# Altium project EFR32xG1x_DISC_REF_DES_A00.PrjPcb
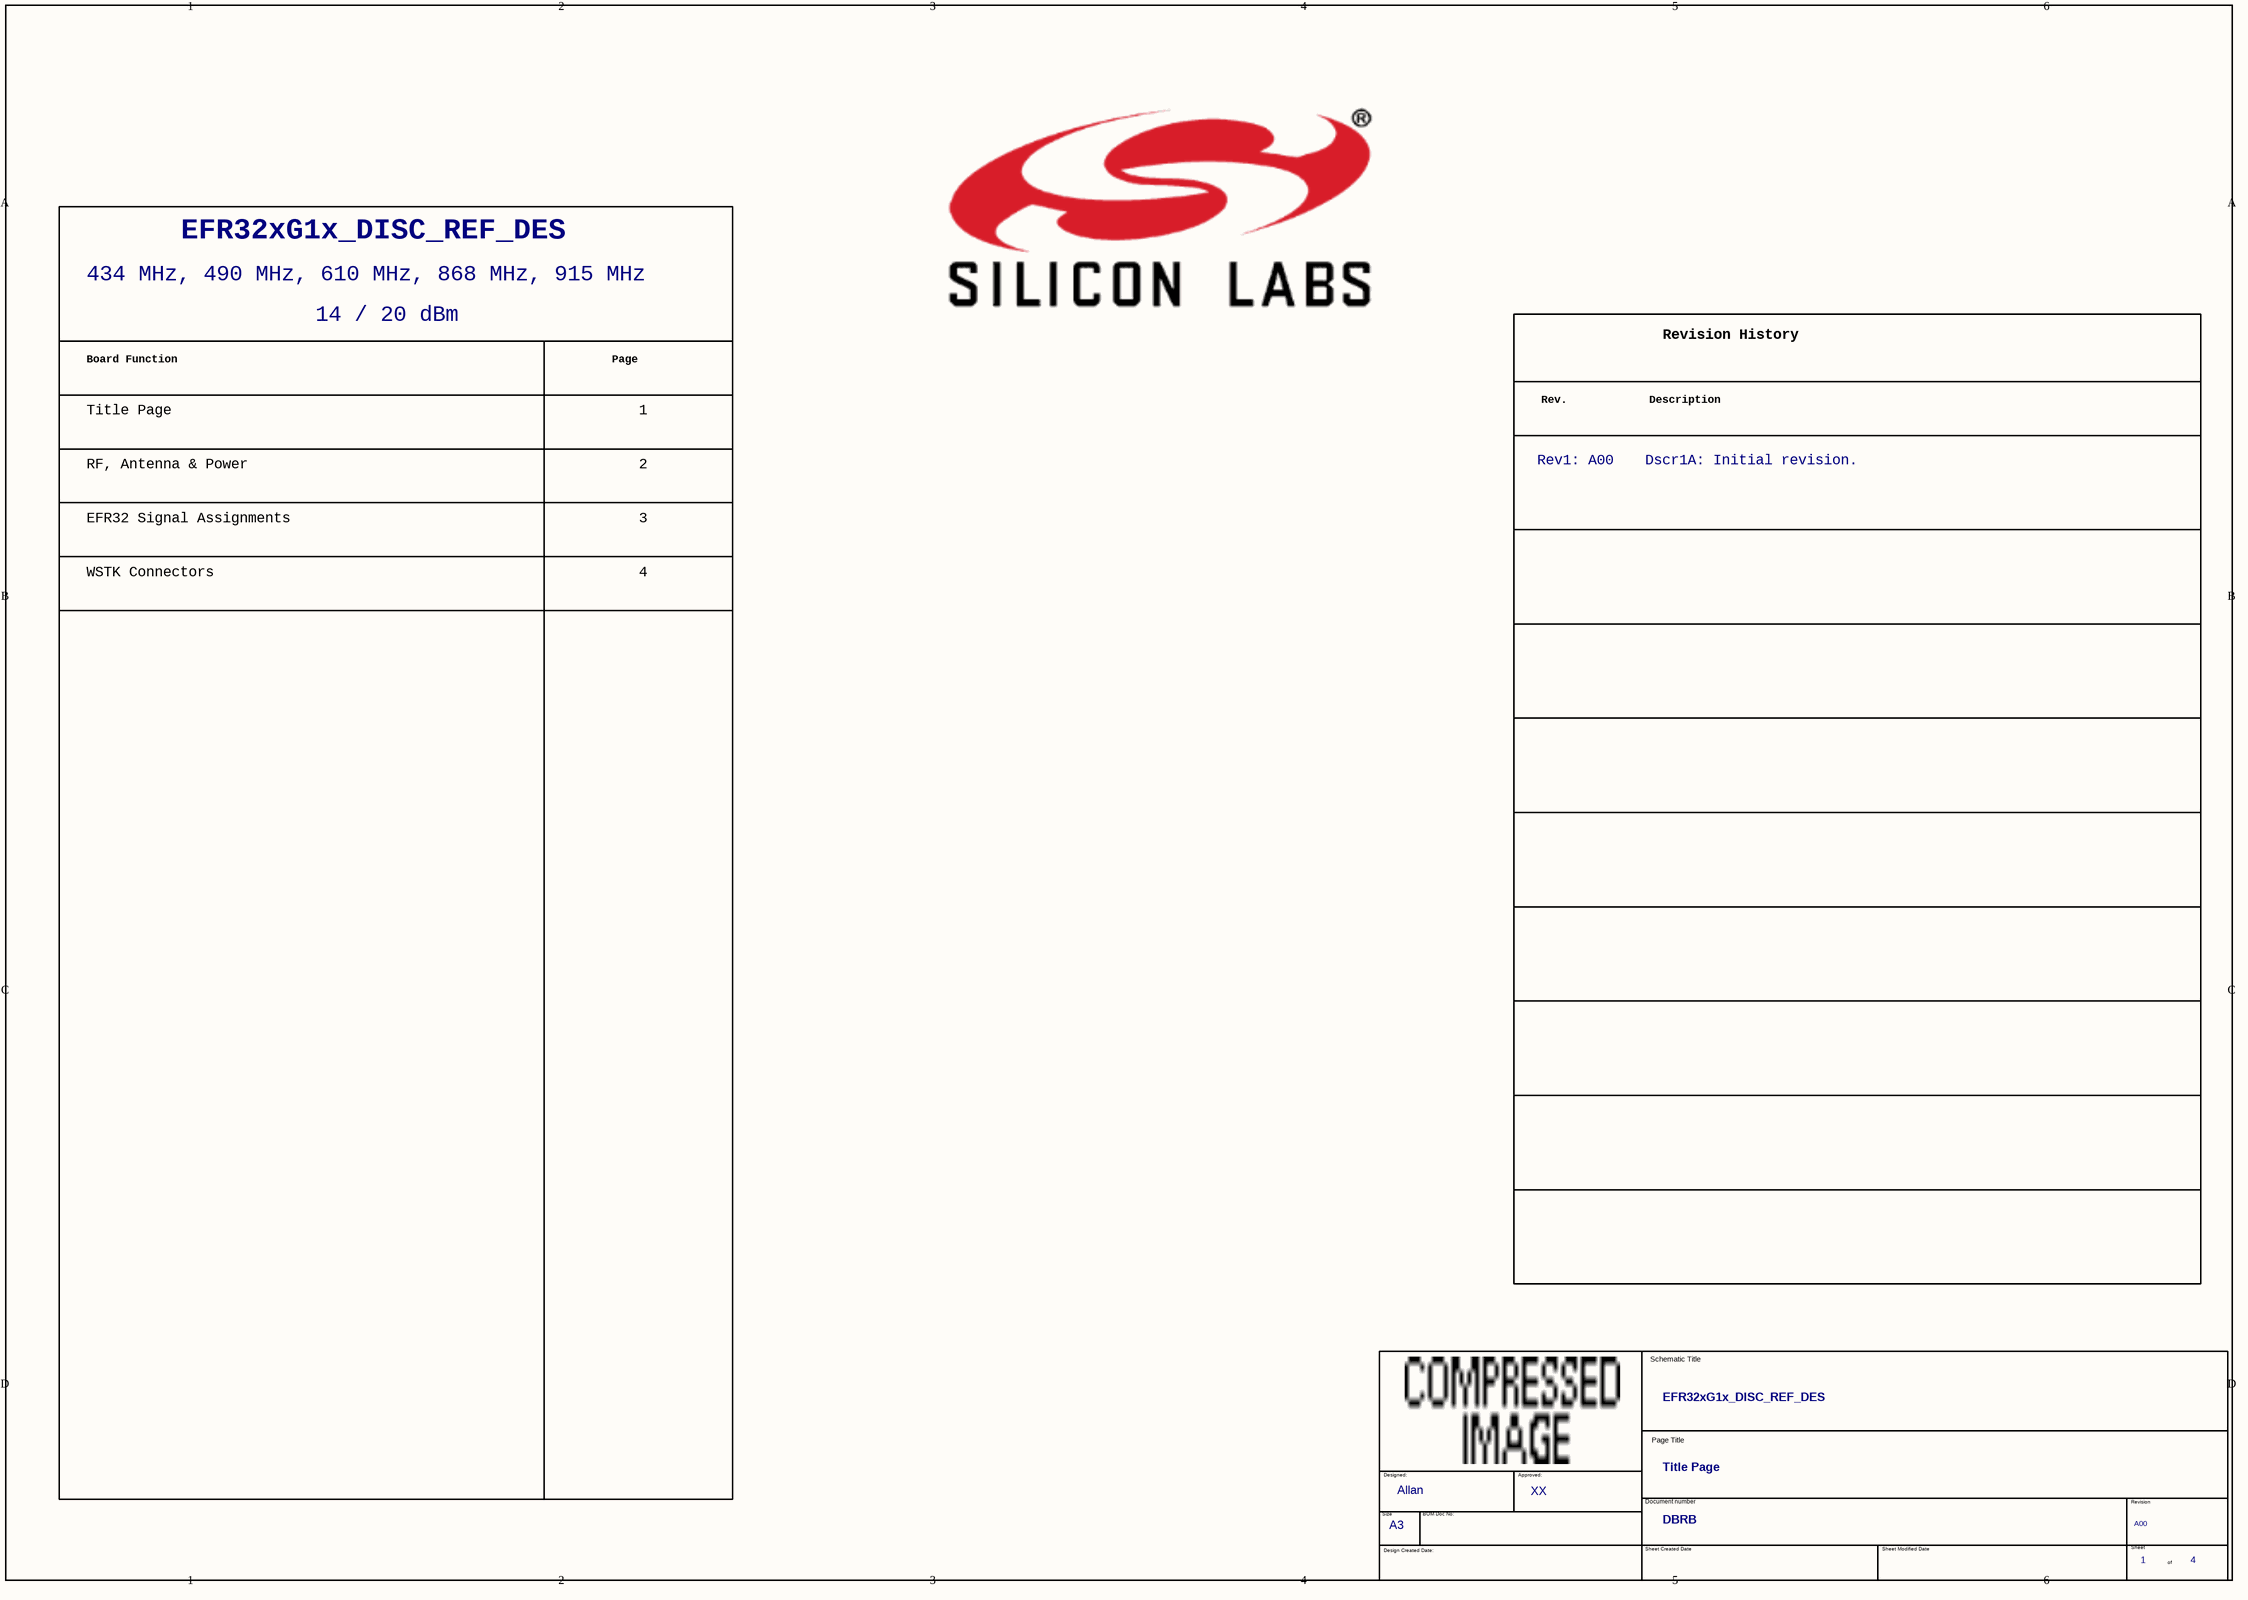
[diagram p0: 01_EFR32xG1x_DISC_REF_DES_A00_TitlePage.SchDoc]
4 sheets, 94 parts. Net scope: global (net labels, ports and power ports of the same name join across sheets).
Board file: EFR32xG1x_DISC_REF_DES_A00.PcbDoc
Sheets:
  01_EFR32xG1x_DISC_REF_DES_A00_TitlePage.SchDoc
  02_EFR32xG1x_DISC_REF_DES_A00_RfAntPower.SchDoc
  03_EFR32xG1x_DISC_REF_DES_A00_Efr32Signal.SchDoc
  04_EFR32xG1x_DISC_REF_DES_A00_Conn.SchDoc

## Sheet 01_EFR32xG1x_DISC_REF_DES_A00_TitlePage.SchDoc
size 420 x 297 mm

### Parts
(Parts that share a designator on the sheet are numbered #1, #2 ... from top to bottom, then left to right.)
*#1  Header A: EFR32xG1x_DISC_REF_DES  (hidden comment: Toc_Header)  (graphical)
*#2  Dscr1A: Initial revision.  Rev1: A00  (hidden comment: Rev_History)  (graphical)
*#3  OrgAddr2: XX  OrgAddr1: Allan  Page Count: 4  Page Number: 1  Doc: DBRB  Title: EFR32xG1x_DISC_REF_DES  RevCode: A00  Page Size: A3  Page Title: Title Page  (hidden comment: TitleBlock_EnergyMicro_A3)  (graphical)

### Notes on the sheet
- 434 MHz, 490 MHz, 610 MHz, 868 MHz, 915 MHz
- 14 / 20 dBm
- Board Function
- Page
- Title Page
- 1
- EFR32 Signal Assignments
- RF, Antenna & Power
- 2
- 3
- WSTK Connectors
- 4

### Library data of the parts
*#1 = Toc_Header: Doc: BRD4259A; Page Count: 5; Page Number: 1; OrgName: Silicon Labs; RevCode: A01
*#2 = Rev_History: Doc: BRD4259A; RevCode: A01; Title: EFR32FG14 2.4 GHz / 434 MHz 10 dBm Radio Board; OrgAddr2: JNO; OrgAddr1: JSH; OrgName: Silicon Labs; Page Number: 1; Page Count: 5

## Sheet 02_EFR32xG1x_DISC_REF_DES_A00_RfAntPower.SchDoc
size 420 x 297 mm
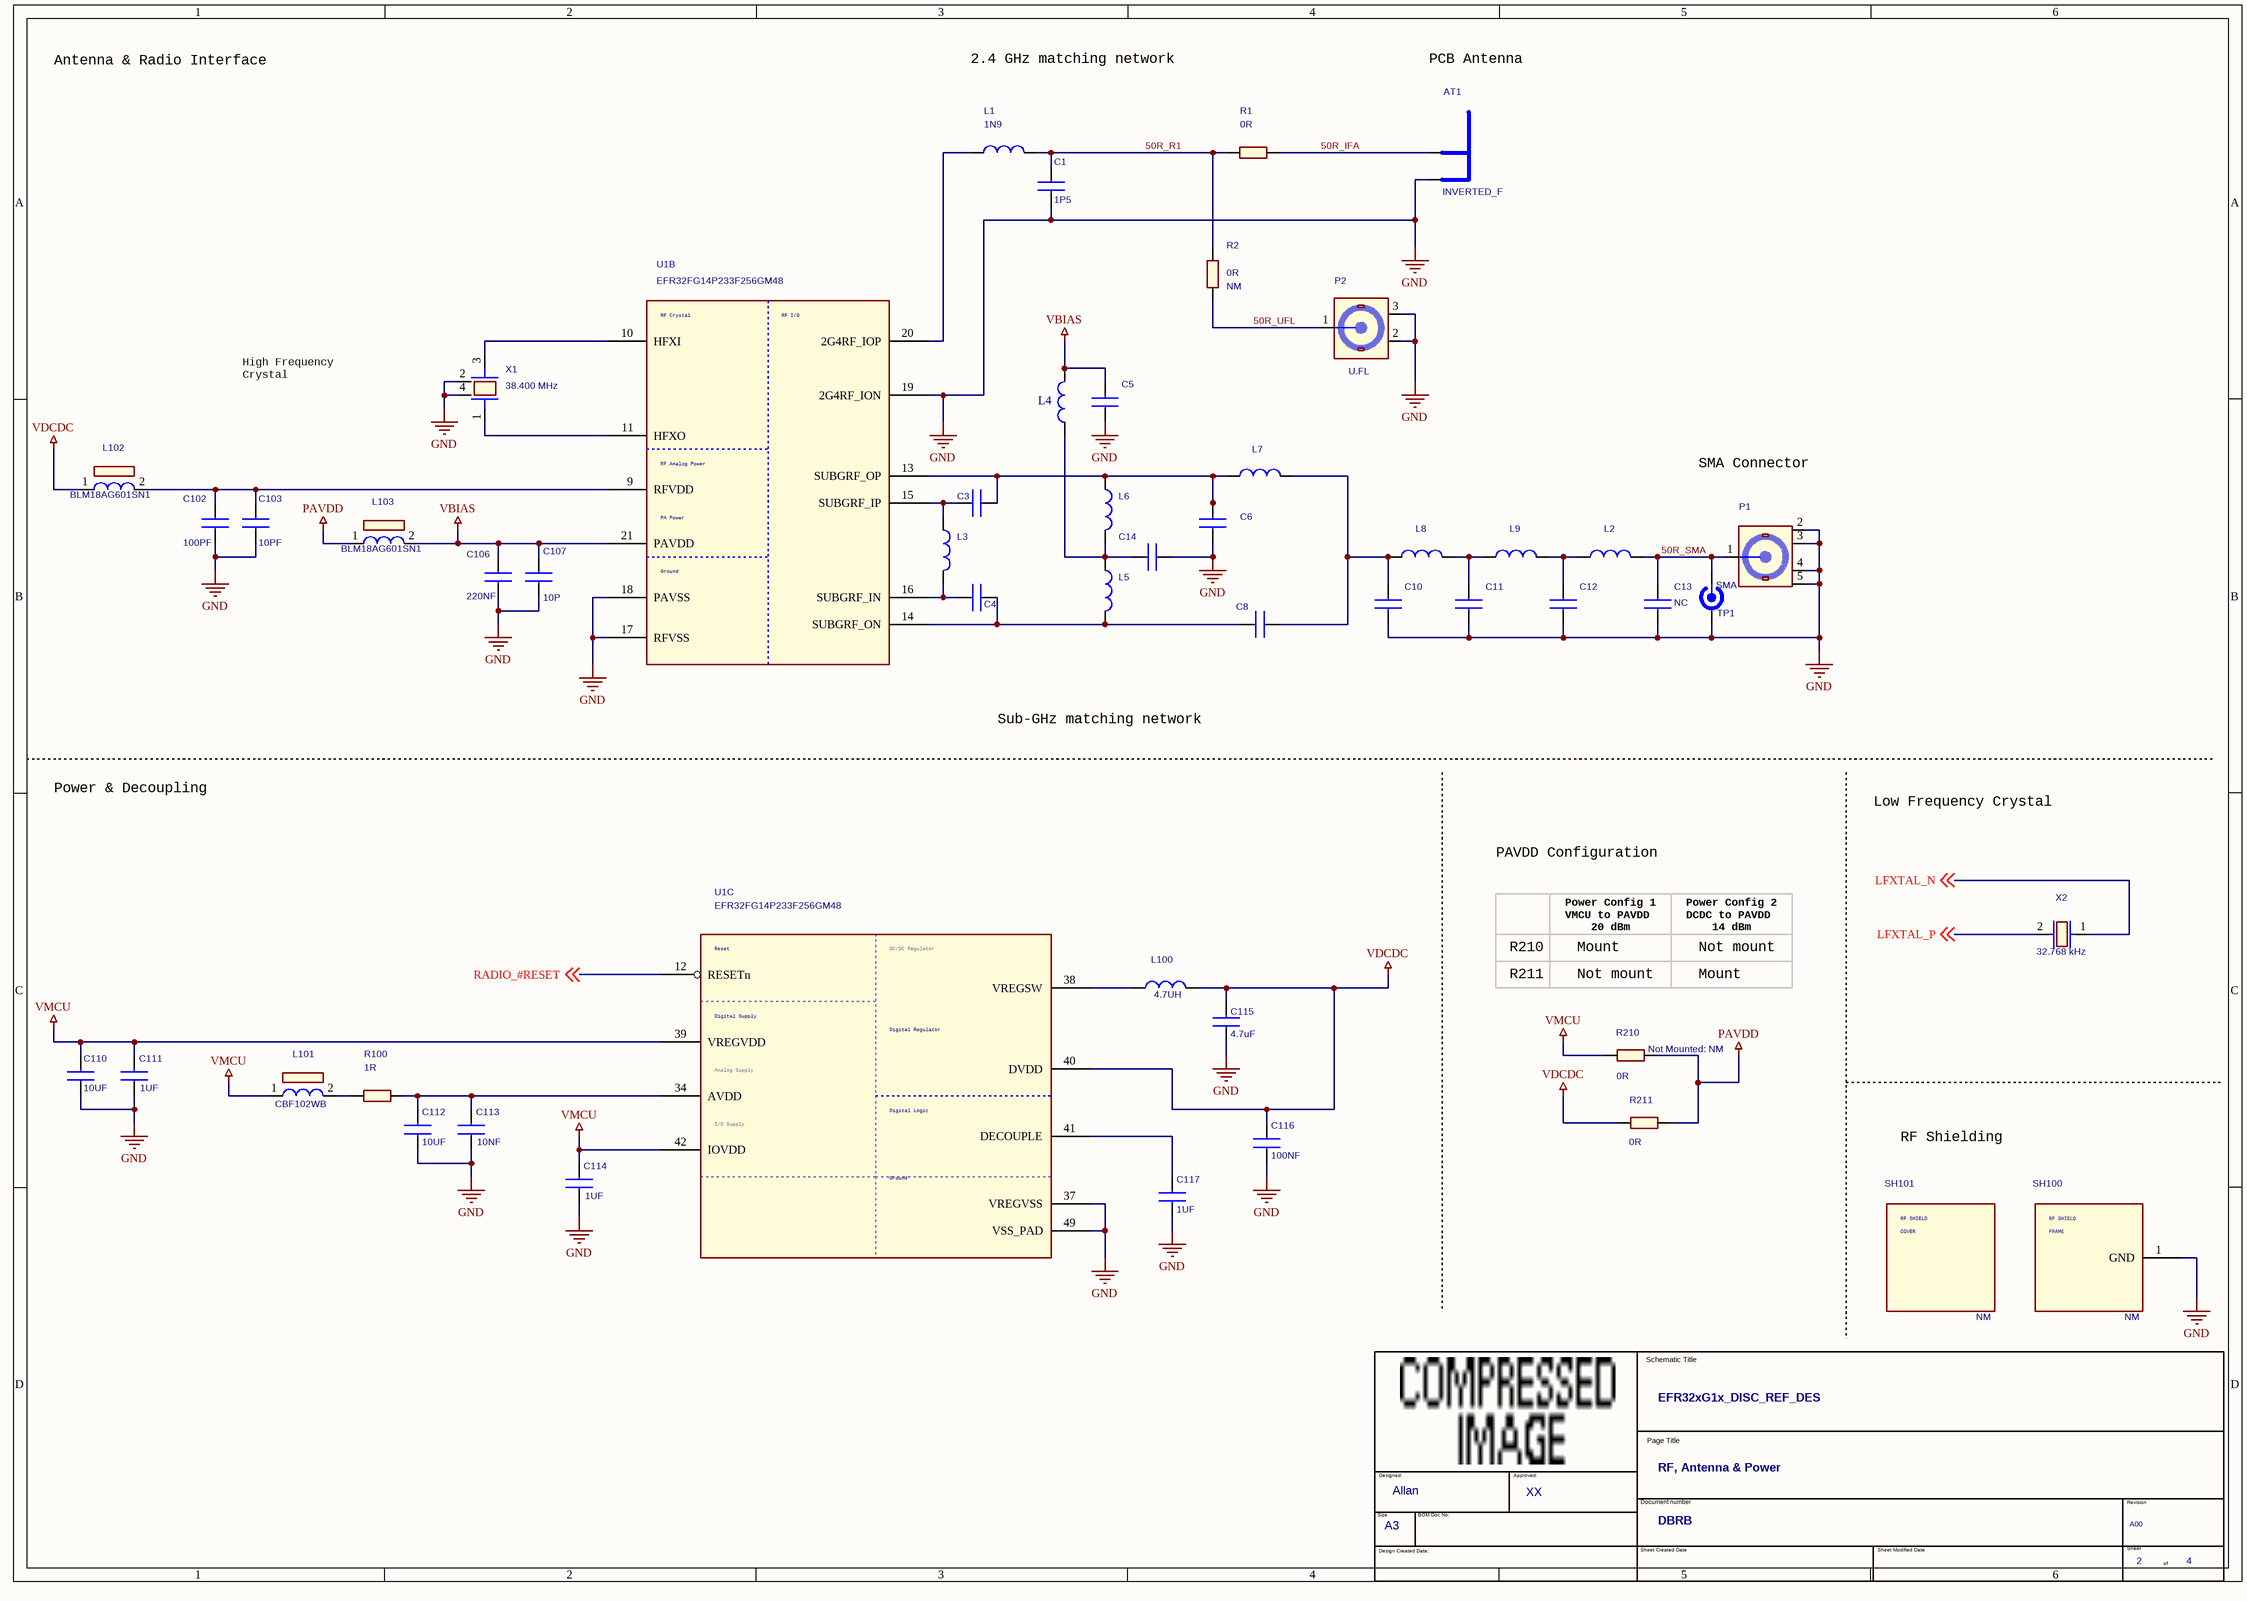
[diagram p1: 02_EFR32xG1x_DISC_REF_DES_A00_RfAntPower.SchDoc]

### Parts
(Parts that share a designator on the sheet are numbered #1, #2 ... from top to bottom, then left to right.)
*#4  OrgAddr2: XX  OrgAddr1: Allan  Page Count: 4  Page Number: 2  Doc: DBRB  Title: EFR32xG1x_DISC_REF_DES  RevCode: A00  Page Size: A3  Page Title: RF, Antenna & Power  (hidden comment: TitleBlock_EnergyMicro_A3)  (graphical)
AT1  INVERTED_F  [ANT_INV_F_2.4_GHZ_17.3MM_MIR]
C1  1P5  [C0201_L]
C3  1P8  [C0201_L]  (value not drawn)
C4  1P8  [C0201_L]  (value not drawn)
C5  270pF  [C0201_L]  (value not drawn)
C6  5.1P  [C0201_L]  (value not drawn)
C8  4P7  [C0201_L]  (value not drawn)
C10  6P2  [C0201_L]  (value not drawn)
C11  5.6P  [C0201_L]  (value not drawn)
C12  5P6  [C0201_L]  (value not drawn)
C13  NC  [C0201_L]
C14  2P  [C0201_L]  (value not drawn)
C102  100PF  [C0402_L]
C103  10PF  [C0402_L]
C106  220NF  [C0402_L]
C107  10P  [C0201_L]
C110  10UF  [C0603_L]
C111  1UF  [C0402_L]
C112  10UF  [C0603_L]
C113  10NF  [C0402_L]
C114  1UF  [C0402_L]
C115  4.7uF  [C0402_L]
C116  100NF  [C0402_L]
C117  1UF  [C0402_L]
L1  1N9  [COIL_0201_L]
L2  120P  [COIL_0201_L]  (value not drawn)
L3  75NH  [COIL_0201_L]  (value not drawn)
L4  330NH  [COIL_0402_L]  (value not drawn)
L5  12NH  [COIL_0201_L]  (value not drawn)
L6  12NH  [COIL_0201_L]  (value not drawn)
L7  27NH  [COIL_0201_L]  (value not drawn)
L8  24NH  [COIL_0201_L]  (value not drawn)
L9  24NH  [COIL_0201_L]  (value not drawn)
L100  4.7UH  [COIL_MUR_LQH3NP_1212]
L101  CBF102WB  [WURTH_CBF_0603]
L102  BLM18AG601SN1  [COIL_MUR_BLM18_0603]
L103  BLM18AG601SN1  [COIL_MUR_BLM18_0603]
P1  SMA  [TE_SMA_TH_1814832]
P2  U.FL  [HIROSE_U.FL-R-SMT-1]
R1  0R  [R0402_L]
R2  0R  Not Mounted: NM  [R0402_L]
R100  1R  [R0402_L]
R210  0R  Not Mounted: NM  [R0402_L]
R211  0R  [R0402_L]
SH100  Not Mounted: NM  [RF_SHIELD_FRAME_BMI-S-203-F_PCB4100]  (hidden comment: RF_SHIELD_FRAME_BMI-S-203-F)
SH101  Not Mounted: NM  (hidden comment: RF_SHIELD_COVER_BMI-S-203-C)
TP1  RF_TEST_POINT  [TP_INGUN_50_OHM_CLOSED openvia]  (value not drawn)
U1  EFR32FG14P233F256GM48  [QFN48_M050_SQ7.0_EP_SL_L]  (parts B,C of 3)
X1  38.400 MHz  [X_SSS_DSX211SH_2.05X1.65-4]
X2  32.768 kHz  [X_MCS_CM8V-T1A]

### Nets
GND: AT1.2(GND) C1.1 C5.2 C6.2 C10.2 C11.2 C12.2 C13.2 C14.2 C102.2 C103.2 C106.2 C107.2 C110.2 C111.2 C112.2 C113.2 C114.2 C115.2 C116.2 C117.2 P1.2(GND1) P1.3(GND2) P1.4(GND3) P1.5(GND4) P2.2(GND1) P2.3(GND4) SH100.1(GND) TP1.2(GND) U1.17(RFVSS) U1.18(PAVSS) U1.19(2G4RF_ION) U1.37(VREGVSS) U1.49(VSS_PAD) X1.2 X1.4
PAVDD: L103.1 R210.1 R211.1
VBIAS: C5.1 C106.1 C107.1 L4.1 L103.2 U1.21(PAVDD)
VDCDC: C115.1 C116.1 L100.2 L102.1 R211.2 U1.40(DVDD)
VMCU: C110.1 C111.1 C114.1 L101.1 R210.2 U1.39(VREGVDD) U1.42(IOVDD)
50R_IFA: AT1.1(ANT) R1.2
50R_R1: C1.2 L1.2 R1.1 R2.1
50R_SMA: C13.1 L2.1 P1.1(SIGNAL) TP1.1(RF)
50R_UFL: P2.1(SIGNAL) R2.2
LFXTAL_N: X2.1 ; off-sheet LFXTAL_N  [project net RADIO_PB15]
LFXTAL_P: X2.2 ; off-sheet LFXTAL_P  [project net RADIO_PB14]
RADIO_#RESET: U1.12(RESETn) ; off-sheet RADIO_#RESET  [project net DEBUG.RESET]
NetC3_1: C3.1 C6.1 L6.1 L7.2 U1.13(SUBGRF_OP)
NetC3_2: C3.2 L3.1 U1.15(SUBGRF_IP)
NetC4_1: C4.1 C8.2 L5.2 U1.14(SUBGRF_ON)
NetC4_2: C4.2 L3.2 U1.16(SUBGRF_IN)
NetC8_1: C8.1 C10.1 L7.1 L8.2
NetC11_1: C11.1 L8.1 L9.2
NetC12_1: C12.1 L2.2 L9.1
NetC14_1: C14.1 L4.2 L5.1 L6.2
NetC102_1: C102.1 C103.1 L102.2 U1.9(RFVDD)
NetC112_1: C112.1 C113.1 R100.2 U1.34(AVDD)
NetC117_1: C117.1 U1.41(DECOUPLE)
NetL1_1: L1.1 U1.20(2G4RF_IOP)
NetL100_1: L100.1 U1.38(VREGSW)
NetL101_2: L101.2 R100.1
NetU1_10: U1.10(HFXI) X1.3
NetU1_11: U1.11(HFXO) X1.1

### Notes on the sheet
- Antenna & Radio Interface
- 2.4 GHz matching network
- PCB Antenna
- High Frequency
  Crystal
- SMA Connector
- Sub-GHz matching network
- Power & Decoupling
- PAVDD Configuration
- Low Frequency Crystal
- Power Config 1
  VMCU to PAVDD
  20 dBm
- Power Config 2
  DCDC to PAVDD
  14 dBm
- R210
- R211
- Not mount
- Mount
- RF Shielding

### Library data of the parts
AT1 = ANT_INVERTED_F
C1 = C0402: Tolerance: ?.05P; Mfg: Murata; Mfg #: GRM1555C1H1R5WA01D
C3 C4 = C0402: Tolerance: ?.05P; Mfg: Murata; Mfg #: GRM1555C1H1R6WA01D
C5 C10 = C0402: Tolerance: ?.1P; Mfg: Murata; Mfg #: GRM1555C1H6R2BA01D
C6 = C0402
C8 C14 = C0402: Tolerance: ?%; Mfg: Murata; Mfg #: GRM1555C1H271FA01D
C11 = C0402: Tolerance: ?%; Mfg: Murata; Mfg #: GRM1555C1H110GA01D
C12 C13 = C0402: Tolerance: ?.05pF; Mfg: Murata; Mfg #: GRM1555C1H5R6WA01D
C102 C103 C107 = C0402: Rating: 50V; Tolerance: 5%
C106 C113 C116 = C0402: Rating: 16V; Tolerance: 10%
C110 C112 = C0603: Rating: 6.3V; Tolerance: 20%
C111 C114 C117 = C0402: Rating: 25V; Tolerance: 10%
C115 = C0402: Rating: 6.3V; Tolerance: 10%
L1 = L0402: Mfg: Murata; Mfg #: LQP15MN1N9W02D; Tolerance: ?.05N
L2 L8 L9 = L0402: Mfg: Murata; Mfg #: LQW15AN24NG00D; Tolerance: ?%
L3 L5 L6 = L0402
L4 = L0603
L7 = L0402: Mfg: Murata; Mfg #: LQW15AN18NG00D; Tolerance: ?%
L100 = LQH3NP: Mfg: Murata; Mfg #: LQH3NPN4R7MM0L
L101 = CBF102WB: Mfg: W黵th Electronics; Mfg #: 74279266
L102 L103 = BLM18AG: Mfg: Murata; Mfg #: BLM18AG601SN1D
P1 = SMA_TH: Mfg #: 5-1814832-1; Mfg: TE Connectivity
P2 = HIROSE_U.FL: Mfg: Hirose; Mfg #: U.FL-R-SMT-1
R1 R2 R100 R210 R211 = R0402
SH100 = RF_SHIELD_FRAME_BMI-S-203-F: Mfg: Laird Technologies
SH101 = RF_SHIELD_COVER_BMI-S-203-C: Mfg: Laird Technologies
TP1 = TP_RF
U1 = EFR32-DUALBAND-QFN48: MFG: Silicon Labs; MFG #: EFR32FG14P233F256GM48-BR
X1 = DSX211SH: Mfg: KDS; Mfg #: DSX211SH 1ZZNAE38400AB0A
X2 = CM8V-T1A: Mfg: KDS; Mfg #: DST210 1TJG125DP1A0012

## Sheet 03_EFR32xG1x_DISC_REF_DES_A00_Efr32Signal.SchDoc
size 420 x 297 mm
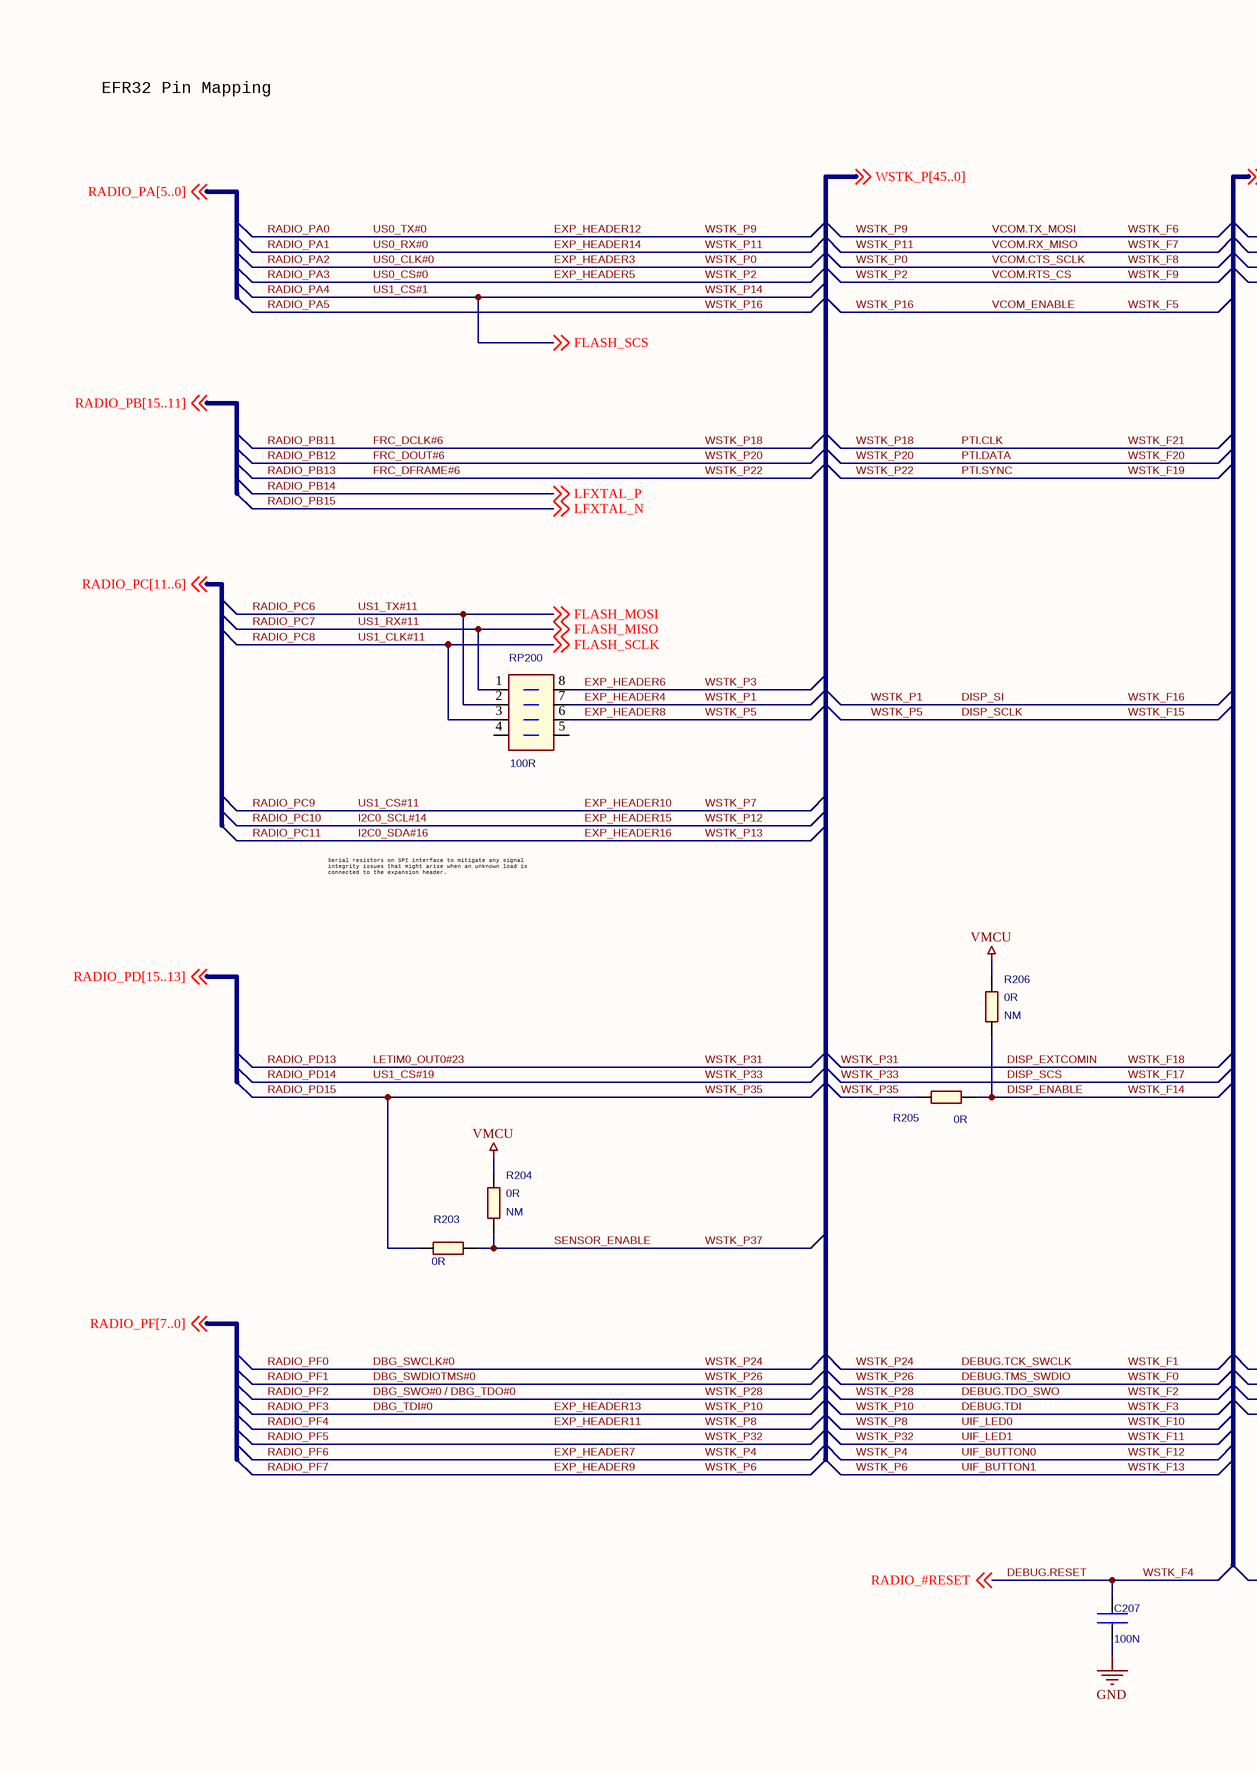
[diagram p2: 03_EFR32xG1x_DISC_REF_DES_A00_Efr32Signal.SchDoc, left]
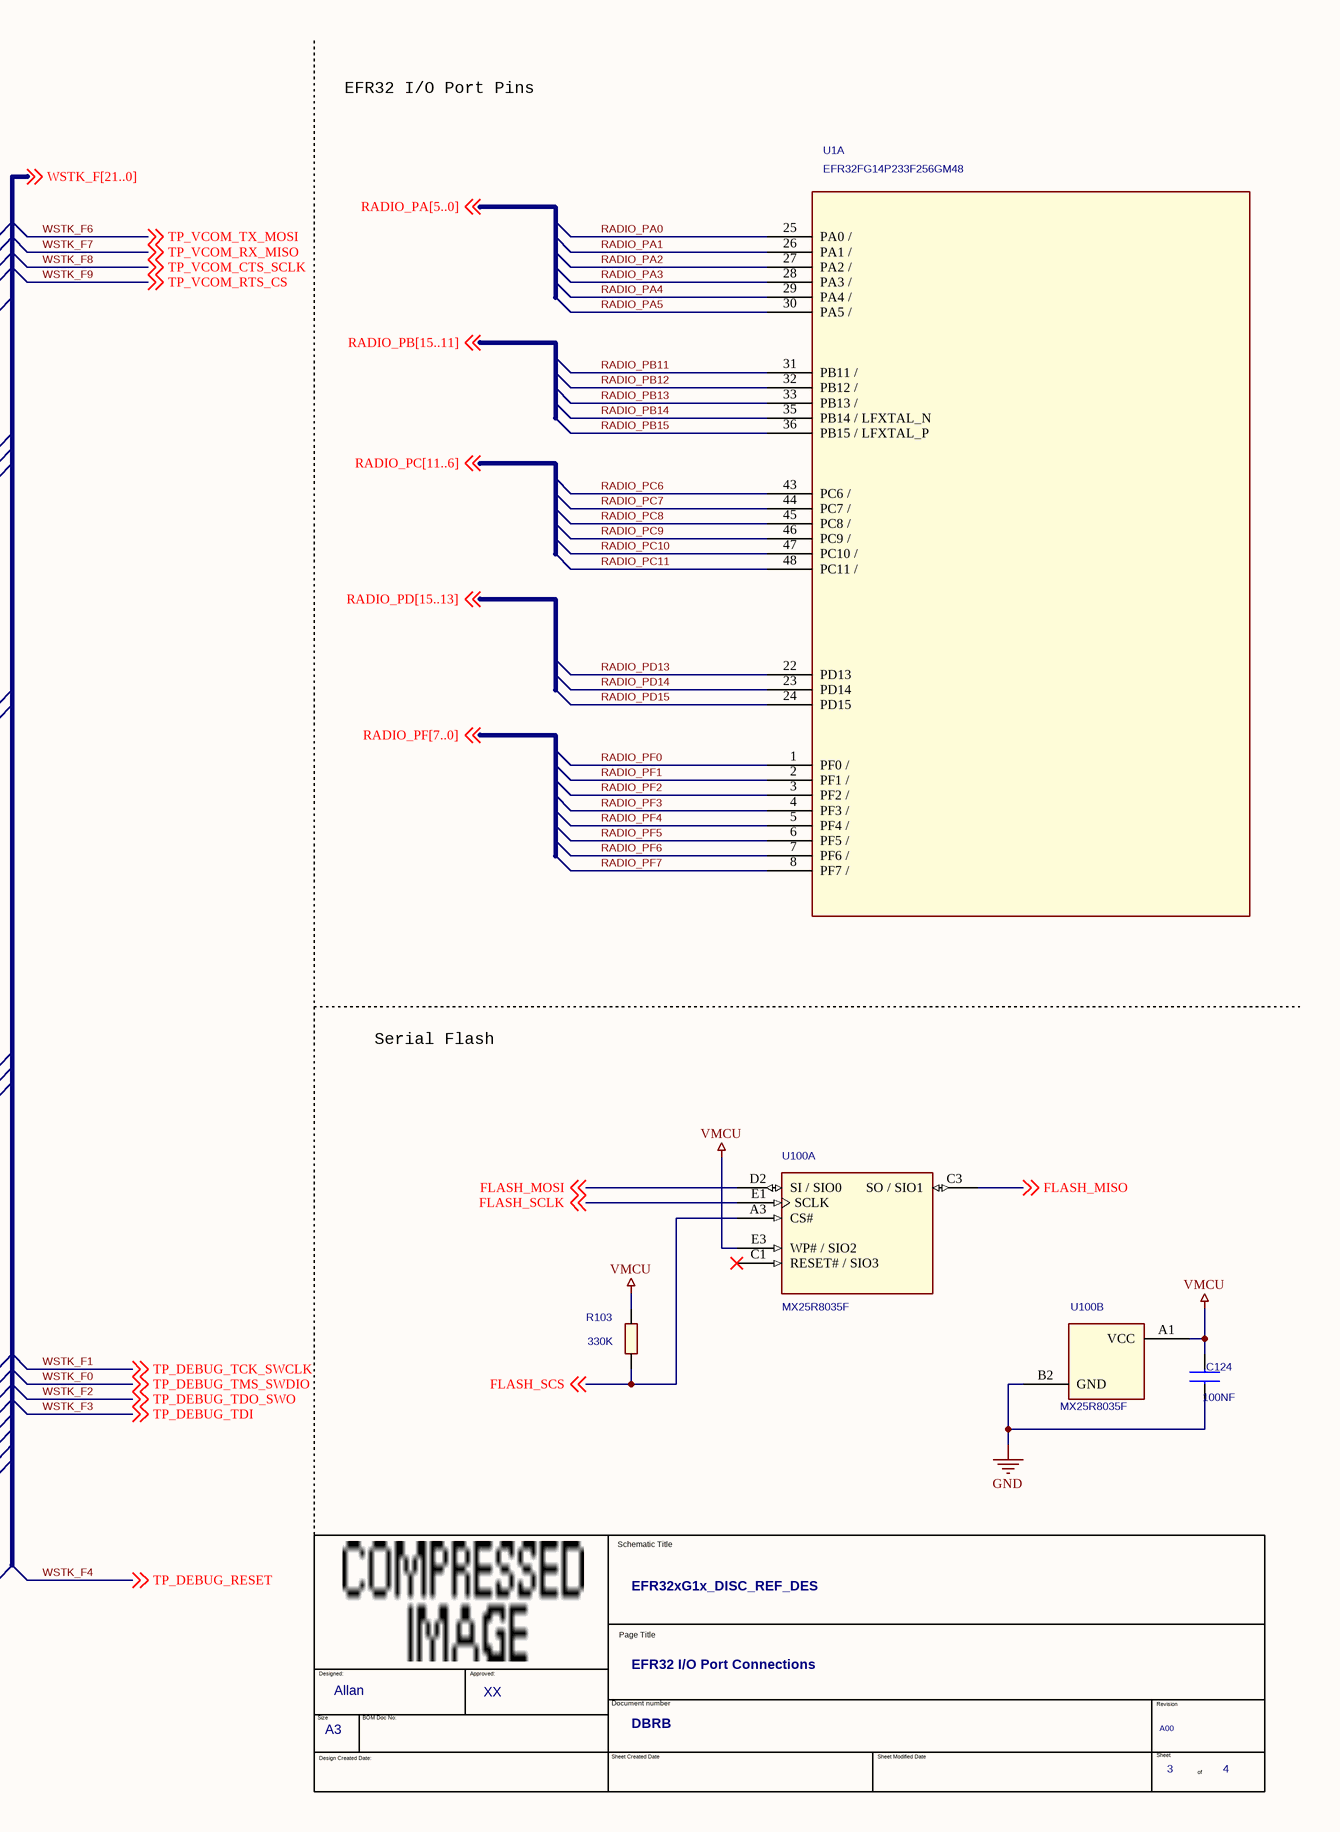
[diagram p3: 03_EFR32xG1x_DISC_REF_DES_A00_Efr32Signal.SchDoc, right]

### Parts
(Parts that share a designator on the sheet are numbered #1, #2 ... from top to bottom, then left to right.)
*#5  OrgAddr2: XX  OrgAddr1: Allan  Page Count: 4  Page Number: 3  Doc: DBRB  Title: EFR32xG1x_DISC_REF_DES  RevCode: A00  Page Size: A3  Page Title: EFR32 I/O Port Connections  (hidden comment: TitleBlock_EnergyMicro_A3)  (graphical)
C124  100NF  [C0402_L]
C207  100N  [C0402_L]
R103  330K  [R0402_L]
R203  0R  [R0402_L]
R204  0R  Not Mounted: NM  [R0402_L]
R205  0R  [R0402_L]
R206  0R  Not Mounted: NM  [R0402_L]
RP200  100R  [RES_MNR04-8]
U1  EFR32FG14P233F256GM48  [QFN48_M050_SQ7.0_EP_SL_L]  (part A of 3)
U100  MX25R8035F  [BGA8_M040_1.24x1.75_WLCSP]  (parts A,B of 2)

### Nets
GND: C124.2 C207.2 U100.B2(GND)
VMCU: C124.1 R103.1 R204.1 R206.1 U100.A1(VCC) U100.E3(WP#_/_SIO2)
DBG_SWCLK#0: U1.1(PF0_/) ; off-sheet TP_DEBUG_TCK_SWCLK  [also labelled DEBUG.TCK_SWCLK, RADIO_PF0, TP_DEBUG_TCK_SWCLK, WSTK_F1, WSTK_P24]
DBG_SWDIOTMS#0: U1.2(PF1_/) ; off-sheet TP_DEBUG_TMS_SWDIO  [also labelled DEBUG.TMS_SWDIO, RADIO_PF1, TP_DEBUG_TMS_SWDIO, WSTK_F0, WSTK_P26]
DBG_SWO#0 / DBG_TDO#0: U1.3(PF2_/) ; off-sheet TP_DEBUG_TDO_SWO  [also labelled DEBUG.TDO_SWO, RADIO_PF2, TP_DEBUG_TDO_SWO, WSTK_F2, WSTK_P28]
DBG_TDI#0: U1.4(PF3_/) ; off-sheet TP_DEBUG_TDI  [also labelled DEBUG.TDI, EXP_HEADER13, RADIO_PF3, TP_DEBUG_TDI, WSTK_F3, WSTK_P10]
DEBUG.RESET: C207.1 ; off-sheet RADIO_#RESET, off-sheet TP_DEBUG_RESET  [also labelled RADIO_#RESET, TP_DEBUG_RESET, WSTK_F4]
DISP_ENABLE: R205.2 R206.2  [also labelled WSTK_F14]
DISP_EXTCOMIN: U1.22(PD13)  [also labelled LETIM0_OUT0#23, RADIO_PD13, WSTK_F18, WSTK_P31]
DISP_SCLK: RP200.6(R16)  [also labelled EXP_HEADER8, WSTK_F15, WSTK_P5]
DISP_SCS: U1.23(PD14)  [also labelled RADIO_PD14, US1_CS#19, WSTK_F17, WSTK_P33]
DISP_SI: RP200.7(R17)  [also labelled EXP_HEADER4, WSTK_F16, WSTK_P1]
EXP_HEADER3: U1.27(PA2_/) ; off-sheet TP_VCOM_CTS_SCLK  [also labelled RADIO_PA2, TP_VCOM_CTS_SCLK, US0_CLK#0, VCOM.CTS_SCLK, WSTK_F8, WSTK_P0]
EXP_HEADER5: U1.28(PA3_/) ; off-sheet TP_VCOM_RTS_CS  [also labelled RADIO_PA3, TP_VCOM_RTS_CS, US0_CS#0, VCOM.RTS_CS, WSTK_F9, WSTK_P2]
EXP_HEADER6: RP200.8(R18)  [also labelled WSTK_P3]
EXP_HEADER7: U1.7(PF6_/)  [also labelled RADIO_PF6, UIF_BUTTON0, WSTK_F12, WSTK_P4]
EXP_HEADER9: U1.8(PF7_/)  [also labelled RADIO_PF7, UIF_BUTTON1, WSTK_F13, WSTK_P6]
EXP_HEADER10: U1.46(PC9_/)  [also labelled RADIO_PC9, US1_CS#11, WSTK_P7]
EXP_HEADER11: U1.5(PF4_/)  [also labelled RADIO_PF4, UIF_LED0, WSTK_F10, WSTK_P8]
EXP_HEADER12: U1.25(PA0_/) ; off-sheet TP_VCOM_TX_MOSI  [also labelled RADIO_PA0, TP_VCOM_TX_MOSI, US0_TX#0, VCOM.TX_MOSI, WSTK_F6, WSTK_P9]
EXP_HEADER14: U1.26(PA1_/) ; off-sheet TP_VCOM_RX_MISO  [also labelled RADIO_PA1, TP_VCOM_RX_MISO, US0_RX#0, VCOM.RX_MISO, WSTK_F7, WSTK_P11]
EXP_HEADER15: U1.47(PC10_/)  [also labelled I2C0_SCL#14, RADIO_PC10, WSTK_P12]
EXP_HEADER16: U1.48(PC11_/)  [also labelled I2C0_SDA#16, RADIO_PC11, WSTK_P13]
FRC_DCLK#6: U1.31(PB11_/)  [also labelled PTI.CLK, RADIO_PB11, WSTK_F21, WSTK_P18]
FRC_DFRAME#6: U1.33(PB13_/)  [also labelled PTI.SYNC, RADIO_PB13, WSTK_F19, WSTK_P22]
FRC_DOUT#6: U1.32(PB12_/)  [also labelled PTI.DATA, RADIO_PB12, WSTK_F20, WSTK_P20]
RADIO_PA4: R103.2 U1.29(PA4_/) U100.A3(CS#) ; off-sheet FLASH_SCS  [also labelled FLASH_SCS, US1_CS#1, WSTK_P14]
RADIO_PA5: U1.30(PA5_/)  [also labelled VCOM_ENABLE, WSTK_F5, WSTK_P16]
RADIO_PB14: U1.35(PB14_/_LFXTAL_N) ; off-sheet LFXTAL_P  [also labelled LFXTAL_P]
RADIO_PB15: U1.36(PB15_/_LFXTAL_P) ; off-sheet LFXTAL_N  [also labelled LFXTAL_N]
RADIO_PC6: RP200.2(R12) U1.43(PC6_/) U100.D2(SI_/_SIO0) ; off-sheet FLASH_MOSI  [also labelled FLASH_MOSI, US1_TX#11]
RADIO_PC7: RP200.1(R11) U1.44(PC7_/) U100.C3(SO_/_SIO1) ; off-sheet FLASH_MISO  [also labelled FLASH_MISO, US1_RX#11]
RADIO_PC8: RP200.3(R13) U1.45(PC8_/) U100.E1(SCLK) ; off-sheet FLASH_SCLK  [also labelled FLASH_SCLK, US1_CLK#11]
RADIO_PD15: R203.1 R205.1 U1.24(PD15)  [also labelled WSTK_P35]
RADIO_PF5: U1.6(PF5_/)  [also labelled UIF_LED1, WSTK_F11, WSTK_P32]
SENSOR_ENABLE: R203.2 R204.2  [also labelled WSTK_P37]

Not connected (* = marked no-connect by the designer): RP200 4(R14) 5(R15); U100 C1(RESET#_/_SIO3)*

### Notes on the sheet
- EFR32 Pin Mapping
- EFR32 I/O Port Pins
- Serial resistors on SPI interface to mitigate any signal
  integrity issues that might arise when an unknown load is
  connected to the expansion header.
- Serial Flash

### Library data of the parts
C124 C207 = C0402: Rating: 16V; Tolerance: 10%
R103 R203-R206 = R0402
RP200 = MNR04M0APJ101: Mfg: ROHM
U1 = EFR32-DUALBAND-QFN48: as U1 on sheet 02_EFR32xG1x_DISC_REF_DES_A00_RfAntPower
U100 = MX25R8035: Mfg: Macronix; Mfg #: MX25R8035FBDIL0

## Sheet 04_EFR32xG1x_DISC_REF_DES_A00_Conn.SchDoc
size 420 x 297 mm
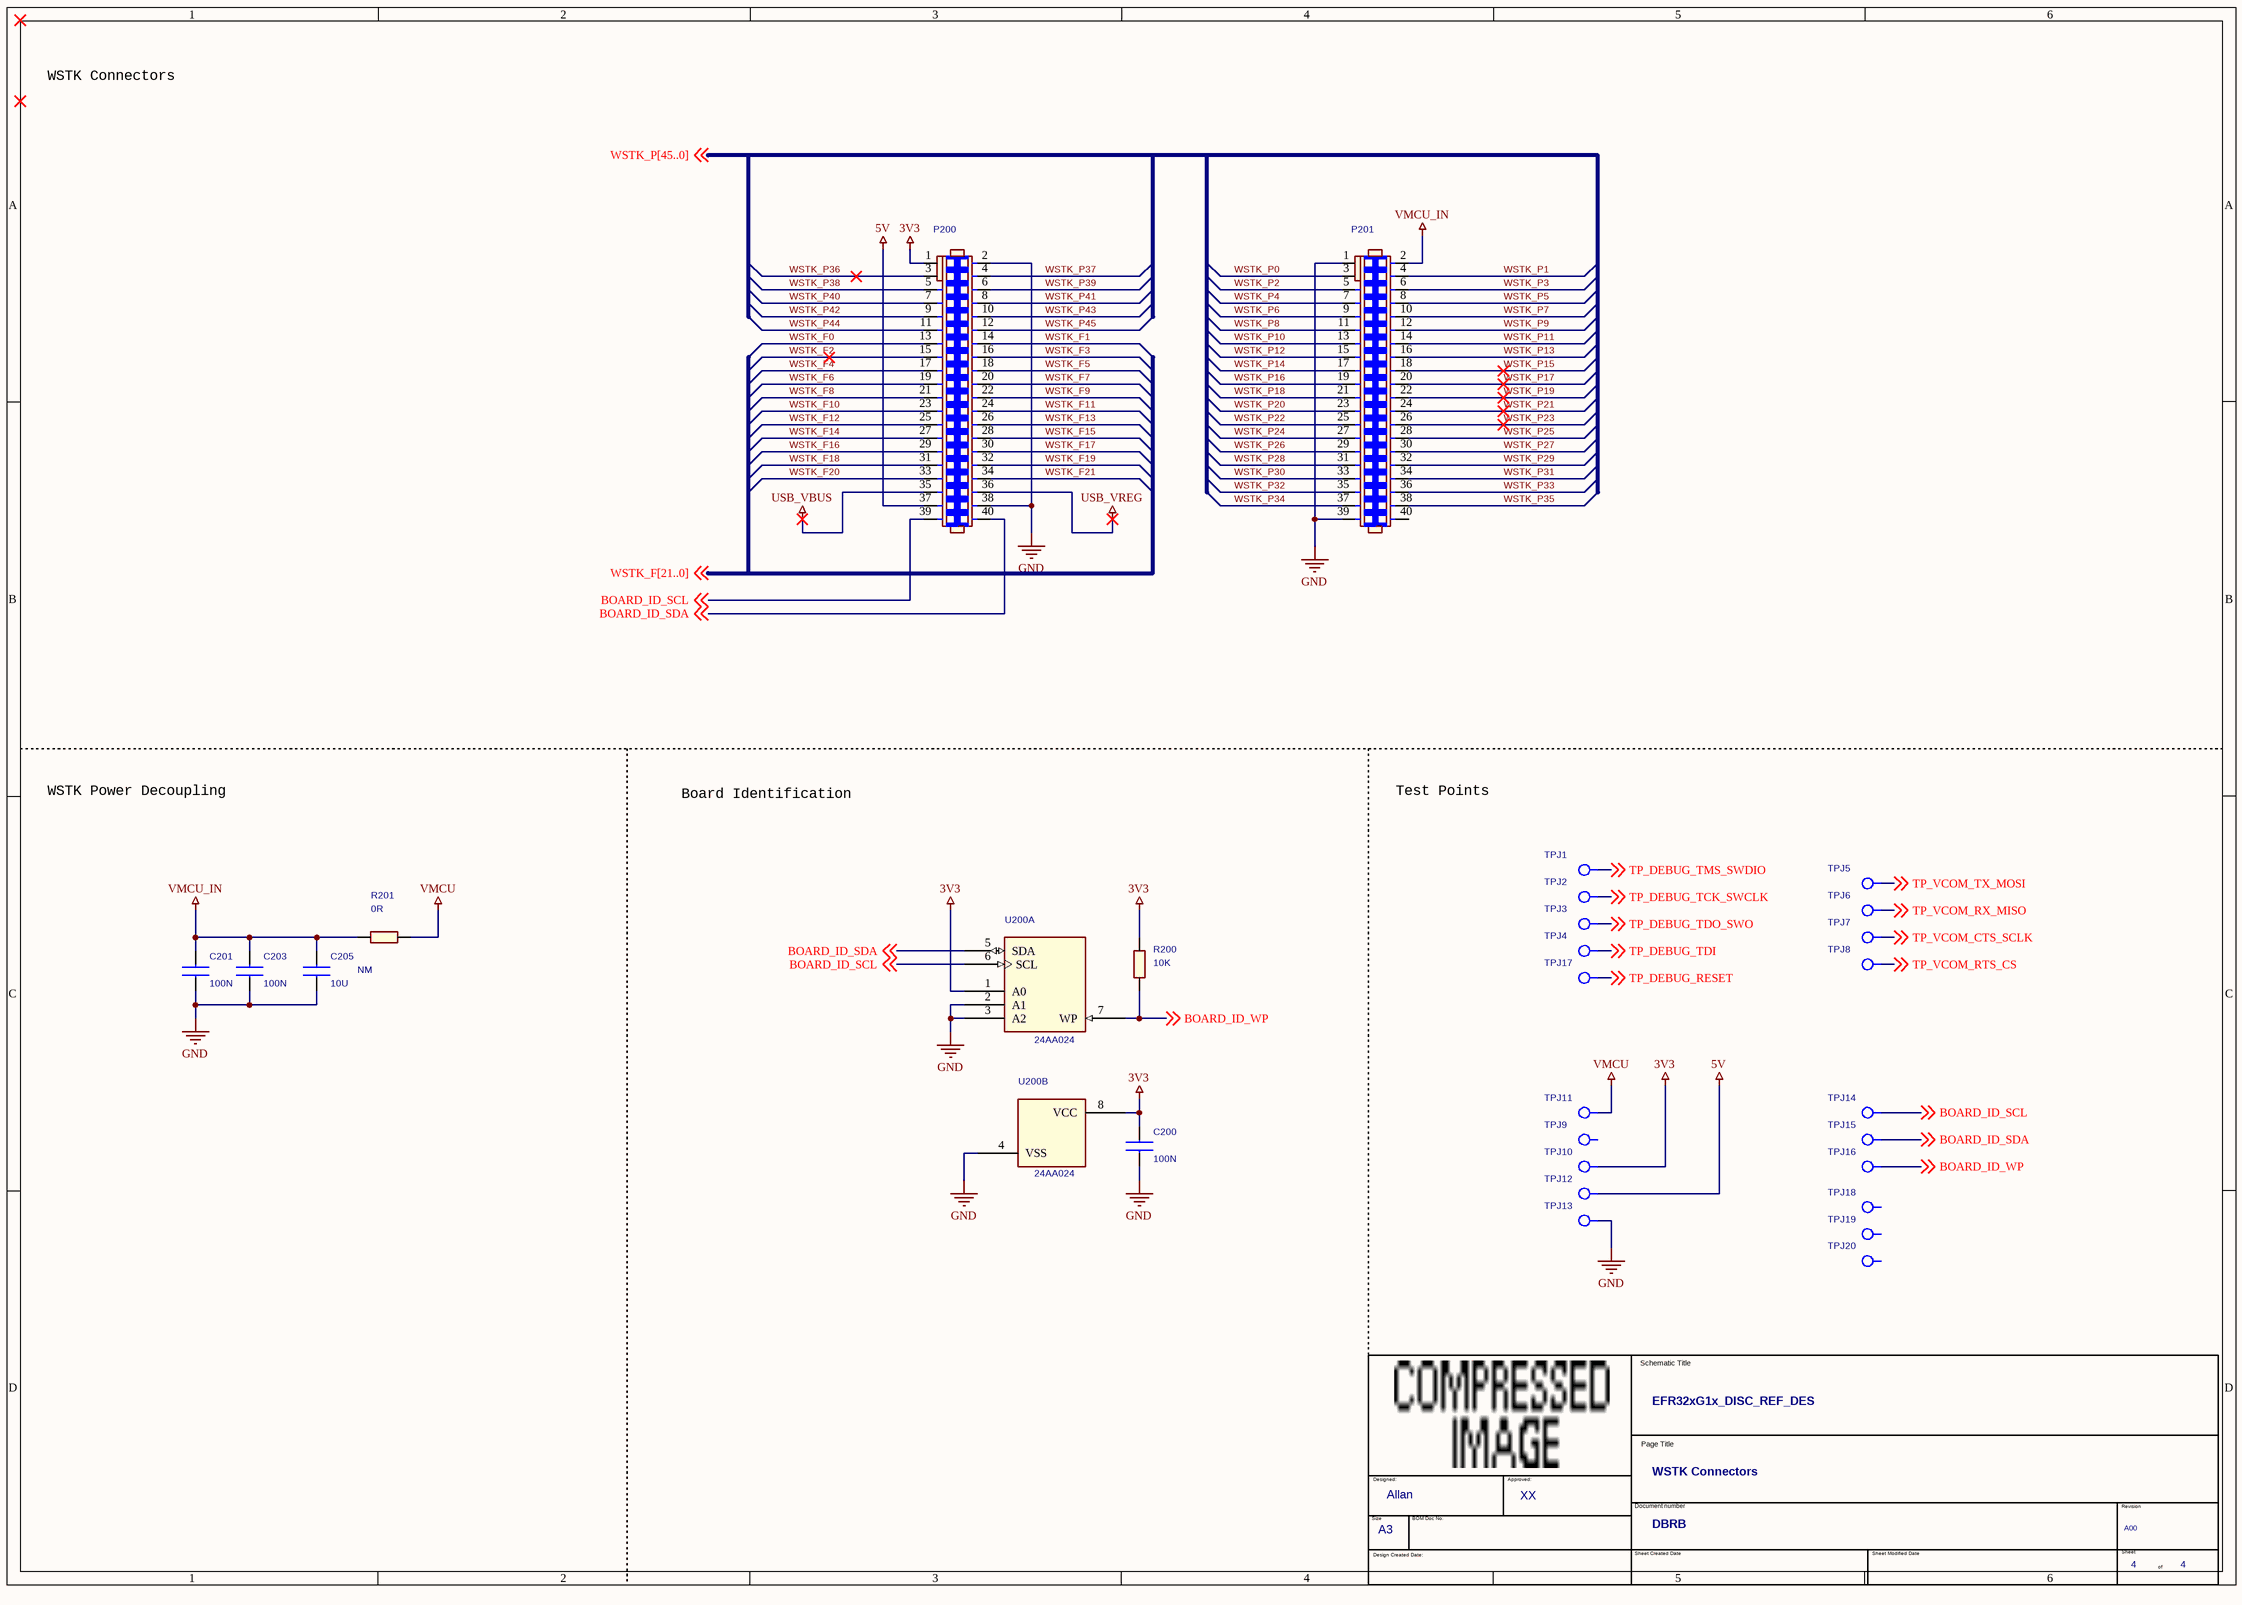
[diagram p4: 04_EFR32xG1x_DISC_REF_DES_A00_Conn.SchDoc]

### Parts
(Parts that share a designator on the sheet are numbered #1, #2 ... from top to bottom, then left to right.)
*#6  OrgAddr2: XX  OrgAddr1: Allan  Page Count: 4  Doc: DBRB  Title: EFR32xG1x_DISC_REF_DES  RevCode: A00  Page Size: A3  Page Title: WSTK Connectors  (hidden comment: TitleBlock_EnergyMicro_A3)  (graphical)
C200  100N  [C0402_L]
C201  100N  [C0402_L]
C203  100N  [C0402_L]
C205  10U  Not Mounted: NM  [C0805_L]
P200  SOCKET_2X20_1.27MM_SMD  [SAM_SFC-120-T2-D-A-2X20_SNUM]  (value not drawn)
P201  SOCKET_2X20_1.27MM_SMD  [SAM_SFC-120-T2-D-A-2X20_SNUM]  (value not drawn)
R200  10K  [R0402_L]
R201  0R  [R0402_L]
TPJ1  TPJ_SMD  [TP_1.0_SMD]  (value not drawn)
TPJ2  TPJ_SMD  [TP_1.0_SMD]  (value not drawn)
TPJ3  TPJ_SMD  [TP_1.0_SMD]  (value not drawn)
TPJ4  TPJ_SMD  [TP_1.0_SMD]  (value not drawn)
TPJ5  TPJ_SMD  [TP_1.0_SMD]  (value not drawn)
TPJ6  TPJ_SMD  [TP_1.0_SMD]  (value not drawn)
TPJ7  TPJ_SMD  [TP_1.0_SMD]  (value not drawn)
TPJ8  TPJ_SMD  [TP_1.0_SMD]  (value not drawn)
TPJ9  TPJ_SMD  [TP_1.0_SMD]  (value not drawn)
TPJ10  TPJ_SMD  [TP_1.0_SMD]  (value not drawn)
TPJ11  TPJ_SMD  [TP_1.0_SMD]  (value not drawn)
TPJ12  TPJ_SMD  [TP_1.0_SMD]  (value not drawn)
TPJ13  TPJ_SMD  [TP_1.0_SMD]  (value not drawn)
TPJ14  TPJ_SMD  [TP_1.0_SMD]  (value not drawn)
TPJ15  TPJ_SMD  [TP_1.0_SMD]  (value not drawn)
TPJ16  TPJ_SMD  [TP_1.0_SMD]  (value not drawn)
TPJ17  TPJ_SMD  [TP_1.0_SMD]  (value not drawn)
TPJ18  TPJ_SMD  [TP_1.0_SMD]  (value not drawn)
TPJ19  TPJ_SMD  [TP_1.0_SMD]  (value not drawn)
TPJ20  TPJ_SMD  [TP_1.0_SMD]  (value not drawn)
U200  24AA024  [TDFN8_M050_2.0X3.0_EP]  (parts A,B of 2)

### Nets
3V3: C200.1 P200.1 R200.2 TPJ10.1(TP) U200.1(A0) U200.8(VCC)
5V: P200.37 TPJ12.1(TP)
GND: C200.2 C201.2 C203.2 C205.2 P200.2 P200.38 P201.1 P201.39 TPJ13.1(TP) U200.2(A1) U200.3(A2) U200.4(VSS)
USB_VBUS: P200.35
USB_VREG: P200.36
VMCU: R201.2 TPJ11.1(TP)
VMCU_IN: C201.1 C203.1 C205.1 P201.2 R201.1
BOARD_ID_SCL: P200.39 TPJ14.1(TP) U200.6(SCL) ; off-sheet BOARD_ID_SCL
BOARD_ID_SDA: P200.40 TPJ15.1(TP) U200.5(SDA) ; off-sheet BOARD_ID_SDA
BOARD_ID_WP: R200.1 TPJ16.1(TP) U200.7(WP) ; off-sheet BOARD_ID_WP
TP_DEBUG_RESET: P200.17 TPJ17.1(TP) ; off-sheet TP_DEBUG_RESET  [also labelled WSTK_F4]  [project net DEBUG.RESET]
TP_DEBUG_TCK_SWCLK: P200.14 P201.27 TPJ2.1(TP) ; off-sheet TP_DEBUG_TCK_SWCLK  [also labelled WSTK_F1, WSTK_P24]  [project net DBG_SWCLK#0]
TP_DEBUG_TDI: P200.16 P201.13 TPJ4.1(TP) ; off-sheet TP_DEBUG_TDI  [also labelled WSTK_F3, WSTK_P10]  [project net DBG_TDI#0]
TP_DEBUG_TDO_SWO: P200.15 P201.31 TPJ3.1(TP) ; off-sheet TP_DEBUG_TDO_SWO  [also labelled WSTK_F2, WSTK_P28]  [project net DBG_SWO#0 / DBG_TDO#0]
TP_DEBUG_TMS_SWDIO: P200.13 P201.29 TPJ1.1(TP) ; off-sheet TP_DEBUG_TMS_SWDIO  [also labelled WSTK_F0, WSTK_P26]  [project net DBG_SWDIOTMS#0]
TP_VCOM_CTS_SCLK: P200.21 P201.3 TPJ7.1(TP) ; off-sheet TP_VCOM_CTS_SCLK  [also labelled WSTK_F8, WSTK_P0]  [project net EXP_HEADER3]
TP_VCOM_RTS_CS: P200.22 P201.5 TPJ8.1(TP) ; off-sheet TP_VCOM_RTS_CS  [also labelled WSTK_F9, WSTK_P2]  [project net EXP_HEADER5]
TP_VCOM_RX_MISO: P200.20 P201.14 TPJ6.1(TP) ; off-sheet TP_VCOM_RX_MISO  [also labelled WSTK_F7, WSTK_P11]  [project net EXP_HEADER14]
TP_VCOM_TX_MOSI: P200.19 P201.12 TPJ5.1(TP) ; off-sheet TP_VCOM_TX_MOSI  [also labelled WSTK_F6, WSTK_P9]  [project net EXP_HEADER12]
WSTK_F5: P200.18 P201.19  [also labelled WSTK_P16]  [project net RADIO_PA5]
WSTK_F10: P200.23 P201.11  [also labelled WSTK_P8]  [project net EXP_HEADER11]
WSTK_F11: P200.24 P201.35  [also labelled WSTK_P32]  [project net RADIO_PF5]
WSTK_F12: P200.25 P201.7  [also labelled WSTK_P4]  [project net EXP_HEADER7]
WSTK_F13: P200.26 P201.9  [also labelled WSTK_P6]  [project net EXP_HEADER9]
WSTK_F14: P200.27  [project net DISP_ENABLE]
WSTK_F15: P200.28 P201.8  [also labelled WSTK_P5]  [project net DISP_SCLK]
WSTK_F16: P200.29 P201.4  [also labelled WSTK_P1]  [project net DISP_SI]
WSTK_F17: P200.30 P201.36  [also labelled WSTK_P33]  [project net DISP_SCS]
WSTK_F18: P200.31 P201.34  [also labelled WSTK_P31]  [project net DISP_EXTCOMIN]
WSTK_F19: P200.32 P201.25  [also labelled WSTK_P22]  [project net FRC_DFRAME#6]
WSTK_F20: P200.33 P201.23  [also labelled WSTK_P20]  [project net FRC_DOUT#6]
WSTK_F21: P200.34 P201.21  [also labelled WSTK_P18]  [project net FRC_DCLK#6]
WSTK_P3: P201.6  [project net EXP_HEADER6]
WSTK_P7: P201.10  [project net EXP_HEADER10]
WSTK_P12: P201.15  [project net EXP_HEADER15]
WSTK_P13: P201.16  [project net EXP_HEADER16]
WSTK_P14: P201.17  [project net RADIO_PA4]
WSTK_P15: P201.18
WSTK_P17: P201.20
WSTK_P19: P201.22
WSTK_P21: P201.24
WSTK_P23: P201.26
WSTK_P25: P201.28
WSTK_P27: P201.30
WSTK_P29: P201.32
WSTK_P30: P201.33
WSTK_P34: P201.37
WSTK_P35: P201.38  [project net RADIO_PD15]
WSTK_P36: P200.3
WSTK_P37: P200.4  [project net SENSOR_ENABLE]
WSTK_P38: P200.5
WSTK_P39: P200.6
WSTK_P40: P200.7
WSTK_P41: P200.8
WSTK_P42: P200.9
WSTK_P43: P200.10
WSTK_P44: P200.11
WSTK_P45: P200.12

Not connected (* = marked no-connect by the designer): P201 40; TPJ9 1(TP); TPJ18 1(TP); TPJ19 1(TP); TPJ20 1(TP)

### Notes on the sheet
- WSTK Connectors
- WSTK Power Decoupling
- Board Identification
- Test Points

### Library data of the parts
C200 C201 C203 = C0402: Rating: 16V; Tolerance: 10%
C205 = C0805: Rating: 10V; Tolerance: 10%
P200 P201 = SOCKET_2X20_1.27MM_SMD: Mfg: Samtec; Mfg #: SFC-120-T2-L-D-A-K-TR
R200 R201 = R0402
U200 = 24AA024: Mfg #: 24AA024T-I/MNY; Mfg: Microchip

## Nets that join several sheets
GND: 02_EFR32xG1x_DISC_REF_DES_A00_RfAntPower (36 pins), 03_EFR32xG1x_DISC_REF_DES_A00_Efr32Signal (C124.2 C207.2 U100.B2), 04_EFR32xG1x_DISC_REF_DES_A00_Conn (12 pins)
VMCU: 02_EFR32xG1x_DISC_REF_DES_A00_RfAntPower (7 pins), 03_EFR32xG1x_DISC_REF_DES_A00_Efr32Signal (6 pins), 04_EFR32xG1x_DISC_REF_DES_A00_Conn (R201.2 TPJ11.1)
DBG_SWCLK#0: 03_EFR32xG1x_DISC_REF_DES_A00_Efr32Signal (U1.1), 04_EFR32xG1x_DISC_REF_DES_A00_Conn (P200.14 P201.27 TPJ2.1)
DBG_SWDIOTMS#0: 03_EFR32xG1x_DISC_REF_DES_A00_Efr32Signal (U1.2), 04_EFR32xG1x_DISC_REF_DES_A00_Conn (P200.13 P201.29 TPJ1.1)
DBG_SWO#0 / DBG_TDO#0: 03_EFR32xG1x_DISC_REF_DES_A00_Efr32Signal (U1.3), 04_EFR32xG1x_DISC_REF_DES_A00_Conn (P200.15 P201.31 TPJ3.1)
DBG_TDI#0: 03_EFR32xG1x_DISC_REF_DES_A00_Efr32Signal (U1.4), 04_EFR32xG1x_DISC_REF_DES_A00_Conn (P200.16 P201.13 TPJ4.1)
DEBUG.RESET: 02_EFR32xG1x_DISC_REF_DES_A00_RfAntPower (U1.12), 03_EFR32xG1x_DISC_REF_DES_A00_Efr32Signal (C207.1), 04_EFR32xG1x_DISC_REF_DES_A00_Conn (P200.17 TPJ17.1)
DISP_ENABLE: 03_EFR32xG1x_DISC_REF_DES_A00_Efr32Signal (R205.2 R206.2), 04_EFR32xG1x_DISC_REF_DES_A00_Conn (P200.27)
DISP_EXTCOMIN: 03_EFR32xG1x_DISC_REF_DES_A00_Efr32Signal (U1.22), 04_EFR32xG1x_DISC_REF_DES_A00_Conn (P200.31 P201.34)
DISP_SCLK: 03_EFR32xG1x_DISC_REF_DES_A00_Efr32Signal (RP200.6), 04_EFR32xG1x_DISC_REF_DES_A00_Conn (P200.28 P201.8)
DISP_SCS: 03_EFR32xG1x_DISC_REF_DES_A00_Efr32Signal (U1.23), 04_EFR32xG1x_DISC_REF_DES_A00_Conn (P200.30 P201.36)
DISP_SI: 03_EFR32xG1x_DISC_REF_DES_A00_Efr32Signal (RP200.7), 04_EFR32xG1x_DISC_REF_DES_A00_Conn (P200.29 P201.4)
EXP_HEADER3: 03_EFR32xG1x_DISC_REF_DES_A00_Efr32Signal (U1.27), 04_EFR32xG1x_DISC_REF_DES_A00_Conn (P200.21 P201.3 TPJ7.1)
EXP_HEADER5: 03_EFR32xG1x_DISC_REF_DES_A00_Efr32Signal (U1.28), 04_EFR32xG1x_DISC_REF_DES_A00_Conn (P200.22 P201.5 TPJ8.1)
EXP_HEADER6: 03_EFR32xG1x_DISC_REF_DES_A00_Efr32Signal (RP200.8), 04_EFR32xG1x_DISC_REF_DES_A00_Conn (P201.6)
EXP_HEADER7: 03_EFR32xG1x_DISC_REF_DES_A00_Efr32Signal (U1.7), 04_EFR32xG1x_DISC_REF_DES_A00_Conn (P200.25 P201.7)
EXP_HEADER9: 03_EFR32xG1x_DISC_REF_DES_A00_Efr32Signal (U1.8), 04_EFR32xG1x_DISC_REF_DES_A00_Conn (P200.26 P201.9)
EXP_HEADER10: 03_EFR32xG1x_DISC_REF_DES_A00_Efr32Signal (U1.46), 04_EFR32xG1x_DISC_REF_DES_A00_Conn (P201.10)
EXP_HEADER11: 03_EFR32xG1x_DISC_REF_DES_A00_Efr32Signal (U1.5), 04_EFR32xG1x_DISC_REF_DES_A00_Conn (P200.23 P201.11)
EXP_HEADER12: 03_EFR32xG1x_DISC_REF_DES_A00_Efr32Signal (U1.25), 04_EFR32xG1x_DISC_REF_DES_A00_Conn (P200.19 P201.12 TPJ5.1)
EXP_HEADER14: 03_EFR32xG1x_DISC_REF_DES_A00_Efr32Signal (U1.26), 04_EFR32xG1x_DISC_REF_DES_A00_Conn (P200.20 P201.14 TPJ6.1)
EXP_HEADER15: 03_EFR32xG1x_DISC_REF_DES_A00_Efr32Signal (U1.47), 04_EFR32xG1x_DISC_REF_DES_A00_Conn (P201.15)
EXP_HEADER16: 03_EFR32xG1x_DISC_REF_DES_A00_Efr32Signal (U1.48), 04_EFR32xG1x_DISC_REF_DES_A00_Conn (P201.16)
FRC_DCLK#6: 03_EFR32xG1x_DISC_REF_DES_A00_Efr32Signal (U1.31), 04_EFR32xG1x_DISC_REF_DES_A00_Conn (P200.34 P201.21)
FRC_DFRAME#6: 03_EFR32xG1x_DISC_REF_DES_A00_Efr32Signal (U1.33), 04_EFR32xG1x_DISC_REF_DES_A00_Conn (P200.32 P201.25)
FRC_DOUT#6: 03_EFR32xG1x_DISC_REF_DES_A00_Efr32Signal (U1.32), 04_EFR32xG1x_DISC_REF_DES_A00_Conn (P200.33 P201.23)
RADIO_PA4: 03_EFR32xG1x_DISC_REF_DES_A00_Efr32Signal (R103.2 U1.29 U100.A3), 04_EFR32xG1x_DISC_REF_DES_A00_Conn (P201.17)
RADIO_PA5: 03_EFR32xG1x_DISC_REF_DES_A00_Efr32Signal (U1.30), 04_EFR32xG1x_DISC_REF_DES_A00_Conn (P200.18 P201.19)
RADIO_PB14: 02_EFR32xG1x_DISC_REF_DES_A00_RfAntPower (X2.2), 03_EFR32xG1x_DISC_REF_DES_A00_Efr32Signal (U1.35)
RADIO_PB15: 02_EFR32xG1x_DISC_REF_DES_A00_RfAntPower (X2.1), 03_EFR32xG1x_DISC_REF_DES_A00_Efr32Signal (U1.36)
RADIO_PD15: 03_EFR32xG1x_DISC_REF_DES_A00_Efr32Signal (R203.1 R205.1 U1.24), 04_EFR32xG1x_DISC_REF_DES_A00_Conn (P201.38)
RADIO_PF5: 03_EFR32xG1x_DISC_REF_DES_A00_Efr32Signal (U1.6), 04_EFR32xG1x_DISC_REF_DES_A00_Conn (P200.24 P201.35)
SENSOR_ENABLE: 03_EFR32xG1x_DISC_REF_DES_A00_Efr32Signal (R203.2 R204.2), 04_EFR32xG1x_DISC_REF_DES_A00_Conn (P200.4)

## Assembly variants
Variant of EFR32xG1x_DISC_REF_DES_A00_434MHz: all parts fitted
Variant of EFR32xG1x_DISC_REF_DES_A00_490MHz: all parts fitted
Variant of EFR32xG1x_DISC_REF_DES_A00_868MHz: all parts fitted
Variant of EFR32xG1x_DISC_REF_DES_A00_915MHz: all parts fitted
Variant of EFR32xG1x_DISC_REF_DES_A00_868&915MHz compatible: all parts fitted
